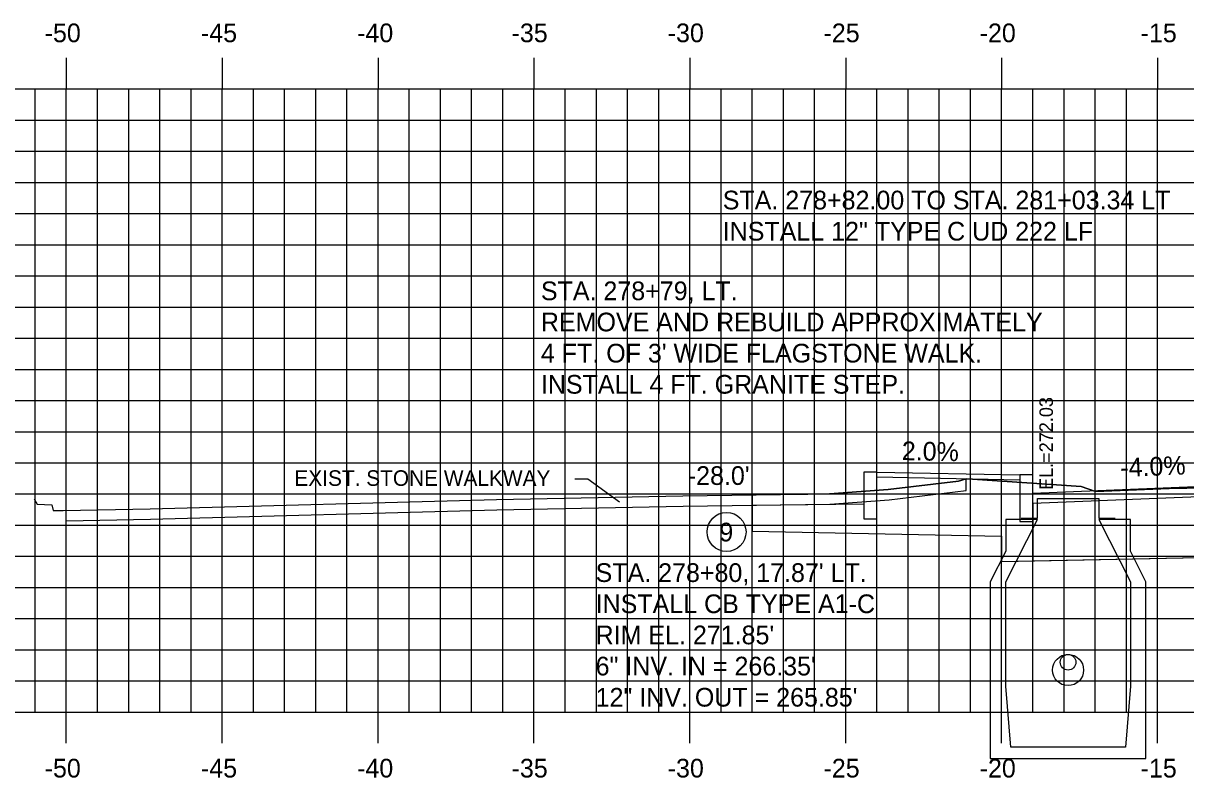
# Model space of a CAD drawing. Extents: x 854676 to 854846, y 366268 to 366378.
# Drawn here: x 854707.72 to 854745.01, y 366323.02 to 366347.24 of the extents above; entities that cross this region are included whole.
import ezdxf

# ---------------------------------------------------------------- set-up
doc = ezdxf.new("R2010")
doc.units = 0
for name, color, linetype in [('ANNOTATION', 7, 'Continuous'), ('D_Curb_Type_1_Lt', 7, 'Continuous'), ('D_Drainage_CB_TypeA1-B1', 7, 'Continuous'), ('D_Drainage_Text', 7, 'Continuous'), ('D_Roadway_Edge_Shoulder', 7, 'Continuous'), ('D_Roadway_Sidewalks_Paved', 7, 'Continuous'), ('D_Roadway_SubGrade', 7, 'Continuous'), ('D_Text_Monospaced', 7, 'Continuous'), ('D_Text_Standard', 7, 'Continuous'), ('H_V ANNOTATION', 7, 'Continuous'), ('JUNK COM EXC', 7, 'Continuous'), ('MAJOR', 7, 'Continuous'), ('MINOR', 7, 'Continuous'), ('PDRAIN', 7, 'Continuous'), ('S_Roadway_Centerline', 7, 'Continuous')]:
    doc.layers.add(name, color=color, linetype=linetype)

msp = doc.modelspace()

# ---------------------------------------------------------------- linework, layer by layer
at = {"layer": 'ANNOTATION'}
msp.add_lwpolyline([(854725.42, 366332.619), (854725.829, 366332.619), (854726.852, 366331.872)], dxfattribs=at)
at = {"layer": 'D_Curb_Type_1_Lt'}
for points in [[(854734.685, 366332.833), (854734.685, 366331.333), (854735.101, 366331.333), (854735.101, 366332.833)], [(854739.69, 366332.741), (854739.69, 366331.241), (854740.106, 366331.241), (854740.106, 366332.741)]]:
    msp.add_lwpolyline(points, close=True, dxfattribs=at)
at = {"layer": 'D_Drainage_CB_TypeA1-B1'}
for p, q in [((854739.235, 366331.313), (854739.235, 366330.296)), ((854739.235, 366329.312), (854740.252, 366331.313)), ((854740.252, 366331.313), (854739.235, 366331.313)), ((854743.238, 366331.313), (854742.221, 366331.313)), ((854742.221, 366331.313), (854743.238, 366329.312)), ((854743.238, 366330.296), (854743.238, 366331.313)), ((854739.235, 366330.296), (854738.743, 366329.312)), ((854743.73, 366329.312), (854743.238, 366330.296)), ((854738.743, 366329.312), (854738.743, 366323.636)), ((854739.235, 366325.965), (854739.235, 366329.312)), ((854743.238, 366329.312), (854743.238, 366325.965)), ((854743.73, 366323.636), (854743.73, 366329.312)), ((854739.399, 366323.997), (854739.235, 366325.965)), ((854743.238, 366325.965), (854743.074, 366323.997)), ((854743.074, 366323.997), (854739.399, 366323.997)), ((854738.743, 366323.636), (854743.73, 366323.636))]:
    msp.add_line(p, q, dxfattribs=at)
msp.add_lwpolyline([(854739.727, 366331.355), (854740.252, 366331.355), (854740.252, 366331.978), (854742.221, 366331.978), (854742.221, 366331.355), (854742.746, 366331.355)], dxfattribs=at)
at = {"layer": 'D_Drainage_Text'}
msp.add_circle((854730.282, 366330.91), 0.625, dxfattribs=at)
at = {"layer": 'D_Roadway_Edge_Shoulder'}
msp.add_line((854740.106, 366332.158), (854748.106, 366332.478), dxfattribs=at)
at = {"layer": 'D_Roadway_Sidewalks_Paved'}
msp.add_lwpolyline([(854735.101, 366332.833), (854739.69, 366332.741), (854739.69, 366332.575), (854735.101, 366332.666)], close=True, dxfattribs=at)
at = {"layer": 'D_Roadway_SubGrade'}
for p, q in [((854731.106, 366332.097), (854734.685, 366332.148)), ((854731.106, 366332.097), (854731.106, 366330.93)), ((854731.106, 366331.764), (854734.685, 366331.815)), ((854731.106, 366330.93), (854739.106, 366330.77))]:
    msp.add_line(p, q, dxfattribs=at)
msp.add_lwpolyline([(854748.106, 366332.145), (854740.106, 366331.825), (854740.106, 366329.985), (854748.106, 366330.145)], close=True, dxfattribs=at)
msp.add_lwpolyline([(854739.106, 366330.77), (854739.106, 366329.965), (854740.106, 366329.985)], dxfattribs=at)
at = {"layer": 'JUNK COM EXC'}
msp.add_lwpolyline([(854771.23, 366332.218), (854765.539, 366332.337), (854759.638, 366332.473), (854753.787, 366332.38), (854748.442, 366332.38), (854744.482, 366332.301), (854742.111, 366332.207), (854741.654, 366332.372), (854738.169, 366332.607), (854737.972, 366332.619), (854737.723, 366332.54), (854735.471, 366332.268), (854733.583, 366332.132), (854731.106, 366332.097), (854731.106, 366330.93), (854739.106, 366330.77), (854739.106, 366329.965), (854748.106, 366330.145), (854759.089, 366330.208), (854770.11, 366329.988)], dxfattribs=at)
at = {"layer": 'MAJOR'}
for p, q in [((854709.106, 366346.13), (854709.106, 366345.128)), ((854714.106, 366346.13), (854714.106, 366345.128)), ((854719.106, 366346.13), (854719.106, 366345.128)), ((854724.106, 366346.13), (854724.106, 366345.128)), ((854729.106, 366346.13), (854729.106, 366345.128)), ((854734.106, 366346.13), (854734.106, 366345.128)), ((854739.106, 366346.13), (854739.106, 366345.128)), ((854744.106, 366346.13), (854744.106, 366345.128)), ((854689.106, 366345.128), (854829.106, 366345.128)), ((854689.106, 366345.128), (854829.106, 366345.128)), ((854709.106, 366325.128), (854709.106, 366345.128)), ((854714.106, 366325.128), (854714.106, 366345.128)), ((854719.106, 366325.128), (854719.106, 366345.128)), ((854724.106, 366325.128), (854724.106, 366345.128)), ((854729.106, 366325.128), (854729.106, 366345.128)), ((854734.106, 366325.128), (854734.106, 366345.128)), ((854739.106, 366325.128), (854739.106, 366345.128)), ((854744.106, 366325.128), (854744.106, 366345.128)), ((854689.106, 366340.128), (854829.106, 366340.128)), ((854689.106, 366335.128), (854829.106, 366335.128)), ((854689.106, 366330.128), (854829.106, 366330.128)), ((854689.106, 366325.128), (854829.106, 366325.128)), ((854689.106, 366325.128), (854829.106, 366325.128)), ((854709.106, 366324.126), (854709.106, 366325.128)), ((854714.106, 366324.126), (854714.106, 366325.128)), ((854719.106, 366324.126), (854719.106, 366325.128)), ((854724.106, 366324.126), (854724.106, 366325.128)), ((854729.106, 366324.126), (854729.106, 366325.128)), ((854734.106, 366324.126), (854734.106, 366325.128)), ((854739.106, 366324.126), (854739.106, 366325.128)), ((854744.106, 366324.126), (854744.106, 366325.128))]:
    msp.add_line(p, q, dxfattribs=at)
at = {"layer": 'MINOR'}
for p, q in [((854708.106, 366325.128), (854708.106, 366345.128)), ((854710.106, 366325.128), (854710.106, 366345.128)), ((854711.106, 366325.128), (854711.106, 366345.128)), ((854712.106, 366325.128), (854712.106, 366345.128)), ((854713.106, 366325.128), (854713.106, 366345.128)), ((854715.106, 366325.128), (854715.106, 366345.128)), ((854716.106, 366325.128), (854716.106, 366345.128)), ((854717.106, 366325.128), (854717.106, 366345.128)), ((854718.106, 366325.128), (854718.106, 366345.128)), ((854720.106, 366325.128), (854720.106, 366345.128)), ((854721.106, 366325.128), (854721.106, 366345.128)), ((854722.106, 366325.128), (854722.106, 366345.128)), ((854723.106, 366325.128), (854723.106, 366345.128)), ((854725.106, 366325.128), (854725.106, 366345.128)), ((854726.106, 366325.128), (854726.106, 366345.128)), ((854727.106, 366325.128), (854727.106, 366345.128)), ((854728.106, 366325.128), (854728.106, 366345.128)), ((854730.106, 366325.128), (854730.106, 366345.128)), ((854731.106, 366325.128), (854731.106, 366345.128)), ((854732.106, 366325.128), (854732.106, 366345.128)), ((854733.106, 366325.128), (854733.106, 366345.128)), ((854735.106, 366325.128), (854735.106, 366345.128)), ((854736.106, 366325.128), (854736.106, 366345.128)), ((854737.106, 366325.128), (854737.106, 366345.128)), ((854738.106, 366325.128), (854738.106, 366345.128)), ((854740.106, 366325.128), (854740.106, 366345.128)), ((854741.106, 366325.128), (854741.106, 366345.128)), ((854742.106, 366325.128), (854742.106, 366345.128)), ((854743.106, 366325.128), (854743.106, 366345.128)), ((854689.106, 366344.128), (854829.106, 366344.128)), ((854689.106, 366343.128), (854829.106, 366343.128)), ((854689.106, 366342.128), (854829.106, 366342.128)), ((854689.106, 366341.128), (854829.106, 366341.128)), ((854689.106, 366339.128), (854829.106, 366339.128)), ((854689.106, 366338.128), (854829.106, 366338.128)), ((854689.106, 366337.128), (854829.106, 366337.128)), ((854689.106, 366336.128), (854829.106, 366336.128)), ((854689.106, 366334.128), (854829.106, 366334.128)), ((854689.106, 366333.128), (854829.106, 366333.128)), ((854689.106, 366332.128), (854829.106, 366332.128)), ((854689.106, 366331.128), (854829.106, 366331.128)), ((854689.106, 366329.128), (854829.106, 366329.128)), ((854689.106, 366328.128), (854829.106, 366328.128)), ((854689.106, 366327.128), (854829.106, 366327.128)), ((854689.106, 366326.128), (854829.106, 366326.128))]:
    msp.add_line(p, q, dxfattribs=at)
at = {"layer": 'PDRAIN'}
for centre, radius in [((854741.236, 366326.478), 0.5), ((854741.236, 366326.728), 0.25)]:
    msp.add_circle(centre, radius, dxfattribs=at)
at = {"layer": 'S_Roadway_Centerline'}
for p, q in [((854737.972, 366332.235), (854737.972, 366332.619)), ((854709.106, 366331.266), (854709.106, 366331.599))]:
    msp.add_line(p, q, dxfattribs=at)
for points in [[(854708.072, 366331.968), (854708.167, 366331.796), (854708.637, 366331.778), (854708.689, 366331.601), (854709.005, 366331.597), (854711.798, 366331.655), (854722.908, 366331.951), (854728.88, 366332.065), (854733.583, 366332.132), (854735.471, 366332.268), (854737.723, 366332.54), (854737.972, 366332.619), (854738.169, 366332.607), (854741.654, 366332.372), (854742.111, 366332.207), (854744.482, 366332.301), (854748.442, 366332.38), (854753.787, 366332.38), (854759.638, 366332.473), (854765.539, 366332.337), (854771.23, 366332.218)], [(854709.106, 366331.266), (854711.806, 366331.322), (854722.916, 366331.618), (854728.886, 366331.732), (854733.597, 366331.799), (854735.503, 366331.937), (854737.972, 366332.235)]]:
    msp.add_lwpolyline(points, dxfattribs=at)

# ---------------------------------------------------------------- texts
at = {"layer": 'ANNOTATION'}
for s, p in [('STA. 278+79, LT.', (854724.328, 366338.348)), ('REMOVE AND REBUILD APPROXIMATELY', (854724.328, 366337.348)), ("4 FT. OF 3' WIDE FLAGSTONE WALK.", (854724.328, 366336.348)), ('INSTALL 4 FT. GRANITE STEP.', (854724.328, 366335.348))]:
    msp.add_text(s, height=0.6, dxfattribs=at).set_placement(p)
for s, rotation, p in [('2.0%', 358.8542, (854735.899, 366333.217)), ('-4.0%', 2.2906, (854742.922, 366332.671))]:
    msp.add_text(s, height=0.6, rotation=rotation, dxfattribs=at).set_placement(p)
at = {"layer": 'D_Drainage_Text'}
for s, p in [('STA. 278+82.00 TO STA. 281+03.34 LT', (854730.16, 366341.262)), ('INSTALL 12" TYPE C UD 222 LF', (854730.16, 366340.262)), ("STA. 278+80, 17.87' LT.", (854726.083, 366329.304)), ('INSTALL CB TYPE A1-C', (854726.083, 366328.304)), ("RIM EL. 271.85'", (854726.083, 366327.304)), ('6" INV. IN = 266.35\'', (854726.083, 366326.304)), ('12" INV. OUT = 265.85\'', (854726.083, 366325.304))]:
    msp.add_text(s, height=0.6, dxfattribs=at).set_placement(p)
at = {"layer": 'D_Text_Monospaced'}
msp.add_text('EXIST. STONE WALKWAY', height=0.49998, dxfattribs=at).set_placement((854716.422, 366332.389))
at = {"layer": 'D_Text_Standard'}
msp.add_text(' EL.=272.03', height=0.4335, rotation=90, dxfattribs=at).set_placement((854740.75, 366332.096))
msp.add_text("-28.0'", height=0.6, dxfattribs=at).set_placement((854729.04, 366332.419))
at = {"layer": 'H_V ANNOTATION'}
for s, p in [('-50', (854708.411, 366346.628)), ('-45', (854713.424, 366346.628)), ('-40', (854718.432, 366346.628)), ('-35', (854723.387, 366346.628)), ('-30', (854728.395, 366346.628)), ('-25', (854733.392, 366346.628)), ('-20', (854738.4, 366346.628)), ('-15', (854743.563, 366346.628)), ('9', (854730.051, 366330.605)), ('-50', (854708.411, 366323.028)), ('-45', (854713.424, 366323.028)), ('-40', (854718.432, 366323.028)), ('-35', (854723.387, 366323.028)), ('-30', (854728.395, 366323.028)), ('-25', (854733.392, 366323.028)), ('-20', (854738.4, 366323.028)), ('-15', (854743.563, 366323.028))]:
    msp.add_text(s, height=0.6, dxfattribs=at).set_placement(p)

doc.saveas('drawing.dxf')
